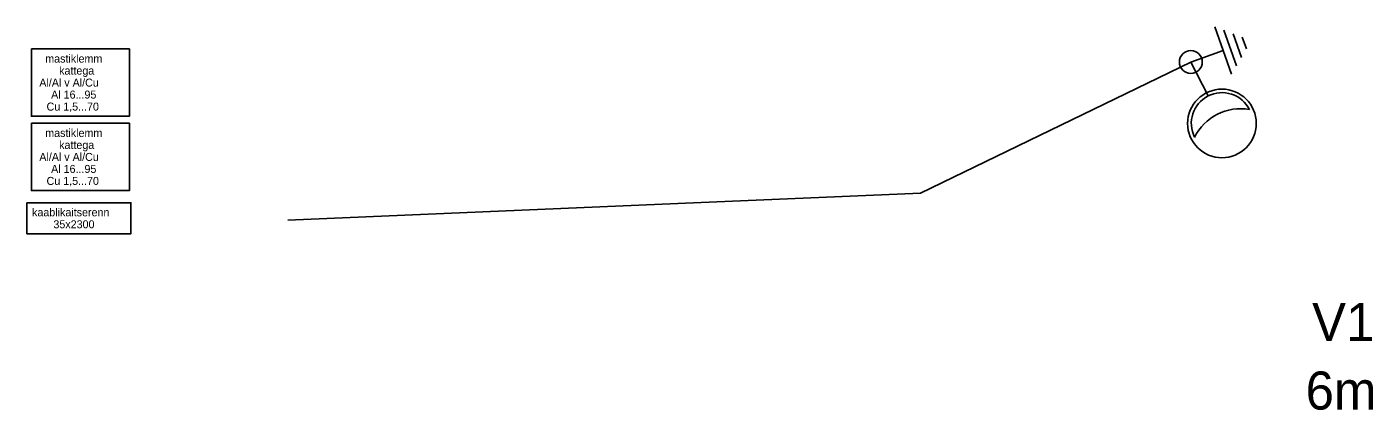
# Model space of a CAD drawing. Extents: x 554241.6 to 554320, y 6593498.2 to 6593528.9.
# Drawn here: x 554241.6 to 554276.93, y 6593498.25 to 6593508.3 of the extents above; entities that cross this region are included whole.
import ezdxf

# ---------------------------------------------------------------- set-up
doc = ezdxf.new("R2010")
doc.units = 0
for name, color, linetype in [('LIKV', 7, 'Continuous'), ('TELG', 7, 'Continuous'), ('V KAABEL TORUS 75mm 450N', 7, 'Continuous'), ('V KAABEL TORUS 75mm 750N', 7, 'Continuous'), ('V MAANDUS', 7, 'Continuous'), ('V MAST 6m', 7, 'Continuous'), ('V TXT', 7, 'Continuous')]:
    doc.layers.add(name, color=color, linetype=linetype)

msp = doc.modelspace()

# ---------------------------------------------------------------- linework, layer by layer
at = {"layer": 'LIKV'}
for points in [[(554241.724, 6593507.725), (554244.295, 6593507.725), (554244.295, 6593505.959), (554241.724, 6593505.959)], [(554241.724, 6593505.775), (554244.295, 6593505.775), (554244.295, 6593504.008), (554241.724, 6593504.008)], [(554241.605, 6593503.687), (554244.335, 6593503.687), (554244.335, 6593502.874), (554241.605, 6593502.874)]]:
    msp.add_lwpolyline(points, close=True, dxfattribs=at)
at = {"layer": 'TELG'}
msp.add_line((554272.145, 6593507.382), (554272.598, 6593506.491), dxfattribs=at)
msp.add_circle((554272.961, 6593505.77), 0.9, dxfattribs=at)
for centre, radius, start, end in [((554272.964, 6593505.771), 0.807, 116.9456, 206.9456), ((554272.964, 6593505.771), 0.807, 26.9456, 116.9456), ((554273.452, 6593504.811), 1.346, 80.0757, 153.8155)]:
    msp.add_arc(centre, radius, start, end, dxfattribs=at)
at = {"layer": 'V KAABEL TORUS 75mm 450N'}
msp.add_lwpolyline([(554258.686, 6593503.668), (554265.052, 6593503.94), (554272.145, 6593507.382)], dxfattribs=at)
at = {"layer": 'V KAABEL TORUS 75mm 750N'}
msp.add_lwpolyline([(554248.452, 6593503.231), (554258.686, 6593503.668)], dxfattribs=at)
at = {"layer": 'V MAANDUS'}
for p, q in [((554273.215, 6593507.063), (554272.775, 6593508.304)), ((554273.344, 6593507.283), (554273.015, 6593508.214)), ((554273.474, 6593507.504), (554273.254, 6593508.124)), ((554273.604, 6593507.724), (554273.494, 6593508.035)), ((554272.145, 6593507.382), (554272.995, 6593507.683))]:
    msp.add_line(p, q, dxfattribs=at)
at = {"layer": 'V MAST 6m'}
msp.add_line((554272.145, 6593507.382), (554272.145, 6593507.382), dxfattribs=at)
msp.add_circle((554272.145, 6593507.382), 0.3, dxfattribs=at)

# ---------------------------------------------------------------- texts
at = {"layer": 'LIKV'}
for s, p in [('mastiklemm', (554242.085, 6593507.367)), ('kattega', (554242.45, 6593507.052)), ('Al/Al v Al/Cu', (554241.93, 6593506.737)), ('Al 16...95', (554242.24, 6593506.422)), ('Cu 1,5...70', (554242.12, 6593506.107)), ('mastiklemm', (554242.085, 6593505.416)), ('kattega', (554242.45, 6593505.101)), ('Al/Al v Al/Cu', (554241.93, 6593504.786)), ('Cu 1,5...70', (554242.12, 6593504.156)), ('Al 16...95', (554242.24, 6593504.471)), ('kaablikaitserenn', (554241.74, 6593503.333)), ('35x2300', (554242.3, 6593503.018))]:
    msp.add_text(s, height=0.21, dxfattribs=at).set_placement(p)
at = {"layer": 'V TXT'}
for s, p in [('V1', (554275.326, 6593500.06)), ('6m', (554275.157, 6593498.26))]:
    msp.add_text(s, height=1, dxfattribs=at).set_placement(p)

doc.saveas('drawing.dxf')
